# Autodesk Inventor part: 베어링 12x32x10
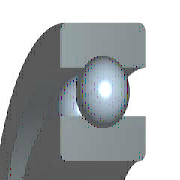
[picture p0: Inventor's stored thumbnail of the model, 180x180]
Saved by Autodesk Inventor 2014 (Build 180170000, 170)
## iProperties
IsCustomPart: 1
Created: 2012-02
Part Number: 베어링 12x32x10
Material: 강철, 연강
Description: 깊은 그루브 볼 베어링
Document SubType Name: Modeling
Standard: KS B 2023
Designer: test
Standards Organization: KS
Language: ko-KR
Size Designation: 6201 - 12 x 32 x 10
Categories: <MemberInstance><Categories><Category DisplayName="샤프트 부품" InternalName="7f7aeb1f-a693-4053-b835-cee3144e0d98" Mnemonic="SHFT"><Category DisplayName="베어링" Inter
Density: 1 g/cm^3
Appearance: Yellow
Author: test
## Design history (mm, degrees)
sketch "스케치" dims "d0" = 5.2 (= -0.26 x WD + 0.26 x BD)
  geometry: L1 (2.4, 11)-(7.6, 11); L2 (5, 11)-(5, 8.4); L3 (5, 11)-(5, 13.6); L4 (3.068, 9.26)-(0, 9.26); L5 (0, 6)-(10, 6); L6 (3.068, 12.74)-(0, 12.74); L7 (0, 16)-(10, 16); L8 (10, 6)-(10, 9.26); L9 (6.932, 9.26)-(10, 9.26); L10 (6.932, 12.74)-(10, 12.74); L11 (10, 16)-(10, 12.74); L12 (-1.4, 0)-(8.4, 0) reference; L13 (0, -0.3)-(0, 5.3) reference
  constraints: 22 end point, 4 point on line, 2 collinear, 2 perpendicular, 2 symmetric about line, 1 midpoint, 1 parallel, 14 other
  dimensions: "d9" = 12 diameter of L5 L12 (= WD); "d11" = 32 diameter of L7 L12 (= BD); "d12" = 10 distance between parallel lines of L8 L13 (= KB); "d13" = 18.52 diameter of L9 L12 (= 0.326 x BD + 0.674 x WD)
revolve "본체" stored, may be unused: angle "d6" = 90 deg
revolve "볼" stored, may be unused: angle "d7" = 90 deg
pattern_circular "IDS_ARRAYBALL[SIMPL:T]" dims angle "d3" = 360 deg
body "Solid1"
fillet "모깎기1" dims "d1" = 0.6 (= KRS)
other parameters: "WD" = 12 [user parameter; used in 5 equation terms], "BD" = 32 [user parameter; used in 5 equation terms], "KB" = 10 [user parameter; used in 1 equation term], "KRS" = 0.6 [user parameter; used in 1 equation term], "d4" = 0, "d5" = 0, "d8" = 0, "d14" = 0, "d15" = 0, "BBA" = 0 [user parameter], "BC0" = 3100000 [user parameter], "BC" = 6890000 [user parameter], "BR" = 16 (= 0.5 x BD) [user parameter], "WR" = 6 (= 0.5 x WD) [user parameter]
